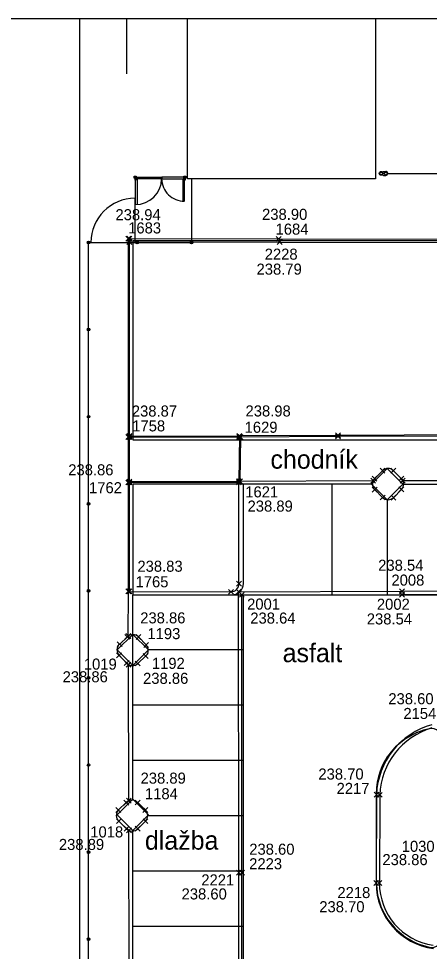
# Model space of a CAD drawing. Extents: x -264165 to -263733, y -1242319 to -1242245.
# Drawn here: x -263975.23 to -263956.67, y -1242287.11 to -1242244.94 of the extents above; entities that cross this region are included whole.
import ezdxf

# ---------------------------------------------------------------- set-up
doc = ezdxf.new("R2010")
doc.units = 0
for name, color, linetype in [('KFA_BOD_CISLO', 7, 'Continuous'), ('KFA_BOD_SYMBOL', 7, 'Continuous'), ('KFA_BOD_VYSKA', 7, 'Continuous'), ('KFA_SO_20-2_OBRUBNIKY_DOLNA_HRANA', 7, 'Continuous'), ('KFA_SO_20-2_OBRUBNIKY_HORNA_HRANA', 7, 'Continuous'), ('POPIS', 7, 'Continuous'), ('PROJEKT_OBRUBNIKY_KOMUNIKACIE', 7, 'Continuous'), ('PROJEKT_TDZ_VODOROVNE', 7, 'Continuous'), ('RAM_NA_TLAC_1-250', 7, 'Continuous'), ('SITUACIA_DSP_2D', 7, 'Continuous')]:
    doc.layers.add(name, color=color, linetype=linetype)

msp = doc.modelspace()

# ---------------------------------------------------------------- linework, layer by layer
at = {"layer": 'KFA_BOD_SYMBOL'}
for p, q in [((-263970.381, -1242254.992), (-263970.16, -1242254.771)), ((-263970.16, -1242254.992), (-263970.381, -1242254.771)), ((-263970.335, -1242254.992), (-263970.114, -1242254.772)), ((-263970.114, -1242254.992), (-263970.335, -1242254.772)), ((-263970.335, -1242255.14), (-263970.114, -1242254.918)), ((-263970.114, -1242255.14), (-263970.335, -1242254.918)), ((-263963.594, -1242255.002), (-263963.372, -1242254.782)), ((-263963.372, -1242255.002), (-263963.594, -1242254.782)), ((-263963.541, -1242255.146), (-263963.319, -1242254.924)), ((-263963.319, -1242255.146), (-263963.541, -1242254.924)), ((-263970.383, -1242263.964), (-263970.161, -1242263.742)), ((-263970.161, -1242263.964), (-263970.383, -1242263.742)), ((-263970.338, -1242263.917), (-263970.117, -1242263.697)), ((-263970.117, -1242263.917), (-263970.338, -1242263.697)), ((-263970.338, -1242263.965), (-263970.117, -1242263.744)), ((-263970.117, -1242263.965), (-263970.338, -1242263.744)), ((-263965.366, -1242263.961), (-263965.144, -1242263.74)), ((-263965.144, -1242263.961), (-263965.366, -1242263.74)), ((-263965.365, -1242263.913), (-263965.144, -1242263.691)), ((-263965.144, -1242263.913), (-263965.365, -1242263.691)), ((-263965.316, -1242263.963), (-263965.095, -1242263.742)), ((-263965.095, -1242263.963), (-263965.316, -1242263.742)), ((-263960.902, -1242263.887), (-263960.681, -1242263.667)), ((-263960.681, -1242263.887), (-263960.902, -1242263.667)), ((-263960.902, -1242263.938), (-263960.681, -1242263.717)), ((-263960.681, -1242263.938), (-263960.902, -1242263.717)), ((-263958.895, -1242265.487), (-263958.674, -1242265.265)), ((-263958.674, -1242265.487), (-263958.895, -1242265.265)), ((-263958.402, -1242265.485), (-263958.181, -1242265.264)), ((-263958.181, -1242265.485), (-263958.402, -1242265.264)), ((-263970.383, -1242266.016), (-263970.161, -1242265.796)), ((-263970.161, -1242266.016), (-263970.383, -1242265.796)), ((-263970.338, -1242265.972), (-263970.117, -1242265.752)), ((-263970.117, -1242265.972), (-263970.338, -1242265.752)), ((-263970.338, -1242266.018), (-263970.117, -1242265.796)), ((-263970.117, -1242266.018), (-263970.338, -1242265.796)), ((-263965.387, -1242265.965), (-263965.166, -1242265.744)), ((-263965.166, -1242265.965), (-263965.387, -1242265.744)), ((-263965.387, -1242266.008), (-263965.166, -1242265.788)), ((-263965.166, -1242266.008), (-263965.387, -1242265.788)), ((-263965.337, -1242265.965), (-263965.116, -1242265.744)), ((-263965.116, -1242265.965), (-263965.337, -1242265.744)), ((-263959.315, -1242265.933), (-263959.094, -1242265.711)), ((-263959.094, -1242265.933), (-263959.315, -1242265.711)), ((-263959.257, -1242265.849), (-263959.035, -1242265.627)), ((-263959.035, -1242265.849), (-263959.257, -1242265.627)), ((-263958.046, -1242265.838), (-263957.825, -1242265.617)), ((-263957.825, -1242265.838), (-263958.046, -1242265.617)), ((-263957.978, -1242265.934), (-263957.757, -1242265.713)), ((-263957.757, -1242265.934), (-263957.978, -1242265.713)), ((-263959.245, -1242266.34), (-263959.024, -1242266.12)), ((-263959.024, -1242266.34), (-263959.245, -1242266.12)), ((-263958.039, -1242266.333), (-263957.818, -1242266.112)), ((-263957.818, -1242266.333), (-263958.039, -1242266.112)), ((-263958.889, -1242266.695), (-263958.667, -1242266.475)), ((-263958.667, -1242266.695), (-263958.889, -1242266.475)), ((-263958.398, -1242266.705), (-263958.177, -1242266.485)), ((-263958.177, -1242266.705), (-263958.398, -1242266.485)), ((-263965.386, -1242270.599), (-263965.165, -1242270.377)), ((-263965.165, -1242270.599), (-263965.386, -1242270.377)), ((-263970.381, -1242270.943), (-263970.16, -1242270.721)), ((-263970.16, -1242270.943), (-263970.381, -1242270.721)), ((-263970.338, -1242270.943), (-263970.117, -1242270.721)), ((-263970.117, -1242270.943), (-263970.338, -1242270.721)), ((-263965.747, -1242270.961), (-263965.525, -1242270.74)), ((-263965.525, -1242270.961), (-263965.747, -1242270.74)), ((-263965.399, -1242270.957), (-263965.178, -1242270.735)), ((-263965.178, -1242270.957), (-263965.399, -1242270.735)), ((-263965.253, -1242271.097), (-263965.032, -1242270.877)), ((-263965.032, -1242271.097), (-263965.253, -1242270.877)), ((-263958.011, -1242270.936), (-263957.79, -1242270.715)), ((-263957.79, -1242270.936), (-263958.011, -1242270.715)), ((-263958.009, -1242271.088), (-263957.788, -1242270.867)), ((-263957.788, -1242271.088), (-263958.009, -1242270.867)), ((-263970.777, -1242273.329), (-263970.556, -1242273.107)), ((-263970.556, -1242273.329), (-263970.777, -1242273.107)), ((-263970.429, -1242272.998), (-263970.208, -1242272.776)), ((-263970.208, -1242272.998), (-263970.429, -1242272.776)), ((-263970.387, -1242272.961), (-263970.166, -1242272.741)), ((-263970.166, -1242272.961), (-263970.387, -1242272.741)), ((-263969.924, -1242273.002), (-263969.703, -1242272.782)), ((-263969.703, -1242273.002), (-263969.924, -1242272.782)), ((-263969.578, -1242273.365), (-263969.356, -1242273.144)), ((-263969.356, -1242273.365), (-263969.578, -1242273.144)), ((-263970.802, -1242273.832), (-263970.581, -1242273.61)), ((-263970.581, -1242273.832), (-263970.802, -1242273.61)), ((-263969.599, -1242273.863), (-263969.378, -1242273.641)), ((-263969.378, -1242273.863), (-263969.599, -1242273.641)), ((-263970.464, -1242274.187), (-263970.242, -1242273.965)), ((-263970.242, -1242274.187), (-263970.464, -1242273.965)), ((-263970.378, -1242274.255), (-263970.156, -1242274.034)), ((-263970.156, -1242274.255), (-263970.378, -1242274.034)), ((-263969.958, -1242274.201), (-263969.736, -1242273.981)), ((-263969.736, -1242274.201), (-263969.958, -1242273.981)), ((-263970.48, -1242280.495), (-263970.258, -1242280.274)), ((-263970.258, -1242280.495), (-263970.48, -1242280.274)), ((-263970.36, -1242280.41), (-263970.139, -1242280.19)), ((-263970.139, -1242280.41), (-263970.36, -1242280.19)), ((-263969.967, -1242280.488), (-263969.746, -1242280.266)), ((-263969.746, -1242280.488), (-263969.967, -1242280.266)), ((-263959.165, -1242280.14), (-263958.943, -1242279.918)), ((-263958.943, -1242280.14), (-263959.165, -1242279.918)), ((-263959.017, -1242280.14), (-263958.796, -1242279.92)), ((-263958.796, -1242280.14), (-263959.017, -1242279.92)), ((-263970.833, -1242280.826), (-263970.611, -1242280.606)), ((-263970.611, -1242280.826), (-263970.833, -1242280.606)), ((-263969.612, -1242280.826), (-263969.391, -1242280.606)), ((-263969.391, -1242280.826), (-263969.612, -1242280.606)), ((-263970.816, -1242281.335), (-263970.595, -1242281.113)), ((-263970.595, -1242281.335), (-263970.816, -1242281.113)), ((-263969.607, -1242281.333), (-263969.386, -1242281.113)), ((-263969.386, -1242281.333), (-263969.607, -1242281.113)), ((-263970.465, -1242281.676), (-263970.244, -1242281.454)), ((-263970.244, -1242281.676), (-263970.465, -1242281.454)), ((-263970.359, -1242281.748), (-263970.138, -1242281.528)), ((-263970.138, -1242281.748), (-263970.359, -1242281.528)), ((-263969.958, -1242281.674), (-263969.736, -1242281.453)), ((-263969.736, -1242281.674), (-263969.958, -1242281.453)), ((-263965.389, -1242283.66), (-263965.168, -1242283.44)), ((-263965.168, -1242283.66), (-263965.389, -1242283.44)), ((-263965.247, -1242283.663), (-263965.026, -1242283.441)), ((-263965.026, -1242283.663), (-263965.247, -1242283.441)), ((-263959.181, -1242284.127), (-263958.959, -1242283.906)), ((-263958.959, -1242284.127), (-263959.181, -1242283.906)), ((-263959.036, -1242284.127), (-263958.815, -1242283.906)), ((-263958.815, -1242284.127), (-263959.036, -1242283.906))]:
    msp.add_line(p, q, dxfattribs=at)
at = {"layer": 'KFA_SO_20-2_OBRUBNIKY_DOLNA_HRANA'}
msp.add_line((-263959.054, -1242280.029), (-263959.07, -1242284.016), dxfattribs=at)
for points in [[(-263970.225, -1242255.029), (-263963.43, -1242255.035), (-263953.224, -1242255.054), (-263930.231, -1242255.088)], [(-263965.289, -1242270.846), (-263957.9, -1242270.825), (-263950.806, -1242270.811), (-263943.808, -1242270.801), (-263936.795, -1242270.772), (-263929.578, -1242270.752)], [(-263965.273, -1242293.566), (-263965.279, -1242283.55), (-263965.289, -1242270.846)], [(-263965.143, -1242270.987), (-263957.899, -1242270.977), (-263950.804, -1242270.956), (-263943.803, -1242270.944), (-263936.794, -1242270.917), (-263929.31, -1242270.895)], [(-263965.127, -1242293.556), (-263965.137, -1242283.552), (-263965.143, -1242270.987)]]:
    msp.add_lwpolyline(points, dxfattribs=at)
for centre, major_axis, ratio, start_param, end_param in [((-263955.655, -1242280.15), (-0.469, 3.371), 0.999366, 0.126889, 1.396912), ((-263956.094, -1242284.026), (2.785, -1.049), 0.999986, 3.498387, 4.942262)]:
    msp.add_ellipse(centre, major_axis=major_axis, ratio=ratio, start_param=start_param, end_param=end_param, dxfattribs=at)
at = {"layer": 'KFA_SO_20-2_OBRUBNIKY_HORNA_HRANA'}
for p, q in [((-263970.27, -1242254.881), (-263970.225, -1242254.882)), ((-263970.227, -1242263.807), (-263965.254, -1242263.802)), ((-263970.227, -1242263.854), (-263965.255, -1242263.85)), ((-263970.227, -1242265.862), (-263965.276, -1242265.854)), ((-263970.227, -1242265.907), (-263965.276, -1242265.898)), ((-263965.276, -1242265.854), (-263959.204, -1242265.822)), ((-263965.275, -1242270.488), (-263965.276, -1242265.854)), ((-263957.867, -1242265.823), (-263950.988, -1242265.812)), ((-263959.134, -1242266.23), (-263958.778, -1242266.585)), ((-263970.666, -1242273.218), (-263970.318, -1242272.887)), ((-263969.813, -1242272.892), (-263969.467, -1242273.254)), ((-263970.692, -1242273.721), (-263970.353, -1242274.076)), ((-263969.488, -1242273.752), (-263969.847, -1242274.091)), ((-263970.249, -1242280.3), (-263970.267, -1242274.144)), ((-263958.906, -1242280.03), (-263958.926, -1242284.016)), ((-263970.722, -1242280.716), (-263970.369, -1242280.384)), ((-263969.856, -1242280.377), (-263969.502, -1242280.716)), ((-263970.355, -1242281.565), (-263970.705, -1242281.224)), ((-263969.497, -1242281.223), (-263969.847, -1242281.563)), ((-263970.239, -1242287.847), (-263970.248, -1242281.638))]:
    msp.add_line(p, q, dxfattribs=at)
for points in [[(-263970.27, -1242270.832), (-263970.272, -1242265.906), (-263970.272, -1242263.853), (-263970.27, -1242254.881)], [(-263970.227, -1242270.832), (-263970.227, -1242265.907), (-263970.227, -1242263.854), (-263970.225, -1242254.882)], [(-263970.225, -1242254.882), (-263963.483, -1242254.892), (-263953.227, -1242254.91), (-263930.229, -1242254.938)], [(-263927.032, -1242263.694), (-263929.858, -1242263.715), (-263931.859, -1242263.708), (-263939.843, -1242263.726), (-263948.832, -1242263.749), (-263954.816, -1242263.759), (-263960.791, -1242263.777), (-263965.254, -1242263.802), (-263965.276, -1242265.854)], [(-263927.18, -1242263.745), (-263929.889, -1242263.765), (-263931.859, -1242263.758), (-263939.843, -1242263.776), (-263948.832, -1242263.799), (-263954.816, -1242263.809), (-263960.791, -1242263.827), (-263965.205, -1242263.852), (-263965.226, -1242265.854)], [(-263958.785, -1242265.376), (-263959.146, -1242265.738)], [(-263957.936, -1242265.727), (-263958.291, -1242265.374)], [(-263958.287, -1242266.595), (-263957.928, -1242266.222)], [(-263970.276, -1242272.851), (-263970.27, -1242270.832), (-263965.636, -1242270.85)]]:
    msp.add_lwpolyline(points, dxfattribs=at)
for centre, major_axis, ratio, start_param, end_param in [((-263958.537, -1242265.623), (-0.323, 0.135), 0.999783, 4.328397, 5.895389), ((-263958.886, -1242265.978), (-0.181, -0.304), 0.999535, 4.506104, 6.043127), ((-263958.187, -1242265.979), (-0.251, 0.252), 0.999847, 3.1764, 4.716307), ((-263958.527, -1242266.332), (0.22, -0.28), 0.999969, 4.836879, 6.356561), ((-263965.627, -1242270.498), (0.328, 0.126), 0.999435, 4.318529, 5.945352), ((-263970.068, -1242273.142), (-0.343, 0.098), 0.999556, 4.196305, 5.766372), ((-263970.439, -1242273.482), (-0.048, -0.345), 0.999733, 3.988836, 5.608141), ((-263969.725, -1242273.493), (0.001, -0.352), 0.999056, 0.736918, 2.312272), ((-263970.093, -1242273.839), (0.352, -0.01), 0.999301, 3.910899, 5.513879), ((-263955.636, -1242280.153), (0.058, 3.275), 0.999165, 0.301718, 1.55091), ((-263970.109, -1242280.629), (-0.352, 0.061), 0.99949, 4.094713, 5.698395), ((-263970.467, -1242280.962), (0.236, -0.264), 0.999925, 3.215899, 4.816729), ((-263969.757, -1242280.972), (0.062, 0.356), 0.999459, 4.116697, 5.669865), ((-263970.102, -1242281.31), (-0.343, -0.109), 0.999217, 0.483156, 2.052302), ((-263956.072, -1242284.009), (-2.548, 1.287), 0.999996, 0.470217, 1.888537)]:
    msp.add_ellipse(centre, major_axis=major_axis, ratio=ratio, start_param=start_param, end_param=end_param, dxfattribs=at)
at = {"layer": 'PROJEKT_OBRUBNIKY_KOMUNIKACIE'}
for p, q in [((-263959.275, -1242265.982), (-263970.068, -1242265.982)), ((-263965.068, -1242270.482), (-263965.068, -1242265.982)), ((-263957.861, -1242265.982), (-263951.031, -1242265.982)), ((-263970.065, -1242280.238), (-263970.068, -1242270.982)), ((-263965.568, -1242270.982), (-263929.061, -1242270.982)), ((-263965.068, -1242293.482), (-263965.068, -1242270.982)), ((-263957.228, -1242277.216), (-263957.743, -1242277.494)), ((-263956.668, -1242277.043), (-263957.228, -1242277.216)), ((-263956.58, -1242277.033), (-263956.668, -1242277.043)), ((-263957.743, -1242277.494), (-263958.195, -1242277.867)), ((-263958.195, -1242277.867), (-263958.566, -1242278.321)), ((-263958.566, -1242278.321), (-263958.841, -1242278.838)), ((-263958.841, -1242278.838), (-263959.011, -1242279.399)), ((-263959.011, -1242279.399), (-263959.068, -1242279.982)), ((-263959.068, -1242279.982), (-263959.068, -1242283.982)), ((-263970.068, -1242287.775), (-263970.068, -1242281.649)), ((-263959.068, -1242283.982), (-263959.011, -1242284.565)), ((-263959.011, -1242284.565), (-263958.841, -1242285.126)), ((-263958.841, -1242285.126), (-263958.566, -1242285.644)), ((-263958.566, -1242285.644), (-263958.195, -1242286.098)), ((-263958.195, -1242286.098), (-263957.743, -1242286.471)), ((-263957.743, -1242286.471), (-263957.228, -1242286.749)), ((-263957.228, -1242286.749), (-263956.668, -1242286.922)), ((-263956.668, -1242286.922), (-263956.58, -1242286.932))]:
    msp.add_line(p, q, dxfattribs=at)
for points in [[(-264042.568, -1242294.032), (-263972.468, -1242294.032), (-263972.468, -1242244.935)], [(-263959.097, -1242244.935), (-263959.097, -1242252.182), (-263967.597, -1242252.182), (-263967.597, -1242244.935)], [(-263929.58, -1242254.982), (-263970.077, -1242254.982), (-263970.077, -1242263.982), (-263929.58, -1242263.982), (-263929.58, -1242254.982)], [(-263958.568, -1242265.275), (-263957.861, -1242265.982), (-263958.568, -1242266.689), (-263959.275, -1242265.982), (-263958.568, -1242265.275)], [(-263970.068, -1242265.982), (-263970.068, -1242270.982), (-263965.568, -1242270.982)], [(-263970.068, -1242272.775), (-263969.361, -1242273.482), (-263970.068, -1242274.189), (-263970.775, -1242273.482), (-263970.068, -1242272.775)], [(-263970.068, -1242280.235), (-263969.361, -1242280.942), (-263970.068, -1242281.649), (-263970.775, -1242280.942), (-263970.068, -1242280.235)]]:
    msp.add_lwpolyline(points, dxfattribs=at)
msp.add_arc((-263965.568, -1242270.482), 0.5, 270, 0, dxfattribs=at)
at = {"layer": 'PROJEKT_TDZ_VODOROVNE'}
for p, q in [((-263961.068, -1242265.982), (-263961.068, -1242270.982)), ((-263958.568, -1242266.689), (-263958.568, -1242270.982)), ((-263965.068, -1242273.482), (-263969.361, -1242273.482)), ((-263965.068, -1242275.982), (-263970.068, -1242275.982)), ((-263965.068, -1242278.482), (-263970.068, -1242278.482)), ((-263965.068, -1242280.982), (-263969.401, -1242280.982)), ((-263965.068, -1242283.482), (-263970.068, -1242283.482)), ((-263965.068, -1242285.982), (-263970.068, -1242285.982))]:
    msp.add_line(p, q, dxfattribs=at)
at = {"layer": 'RAM_NA_TLAC_1-250'}
msp.add_line((-263970.363, -1242244.935), (-263970.363, -1242247.435), dxfattribs=at)
msp.add_lwpolyline([(-264165.363, -1242244.935), (-263732.863, -1242244.935), (-263732.863, -1242319.185), (-264165.363, -1242319.185)], close=True, dxfattribs=at)
at = {"layer": 'SITUACIA_DSP_2D'}
for p, q in [((-263972.468, -1242294.032), (-263972.468, -1242244.935)), ((-263972.468, -1242244.935), (-263972.468, -1242244.935)), ((-263967.597, -1242252.182), (-263967.597, -1242244.935)), ((-263967.597, -1242244.935), (-263967.597, -1242244.935)), ((-263967.593, -1242252.182), (-263967.593, -1242244.935)), ((-263967.593, -1242252.182), (-263967.593, -1242244.935)), ((-263959.097, -1242244.935), (-263959.097, -1242244.935)), ((-263959.097, -1242244.935), (-263959.097, -1242252.182)), ((-263959.093, -1242244.935), (-263959.093, -1242252.182)), ((-263959.093, -1242244.935), (-263959.093, -1242252.182)), ((-263958.799, -1242251.862), (-263958.762, -1242251.862)), ((-263958.799, -1242252.002), (-263958.762, -1242252.002)), ((-263958.762, -1242251.862), (-263958.742, -1242251.842)), ((-263958.762, -1242252.002), (-263958.742, -1242252.022)), ((-263958.742, -1242251.842), (-263958.637, -1242251.842)), ((-263958.575, -1242251.932), (-263952.5, -1242251.932)), ((-263970.018, -1242252.152), (-263970.018, -1242252.052)), ((-263970.018, -1242252.052), (-263969.918, -1242252.052)), ((-263969.918, -1242252.152), (-263970.018, -1242252.152)), ((-263970.005, -1242252.14), (-263970.005, -1242252.065)), ((-263970.005, -1242252.065), (-263969.93, -1242252.065)), ((-263969.93, -1242252.14), (-263970.005, -1242252.14)), ((-263969.93, -1242252.14), (-263969.98, -1242252.14)), ((-263969.98, -1242252.14), (-263969.98, -1242252.24)), ((-263969.98, -1242252.24), (-263969.955, -1242252.24)), ((-263969.968, -1242252.152), (-263969.968, -1242252.202)), ((-263969.968, -1242252.202), (-263969.868, -1242252.202)), ((-263969.955, -1242253.327), (-263969.955, -1242252.19)), ((-263969.955, -1242252.19), (-263969.88, -1242252.19)), ((-263969.93, -1242252.065), (-263969.93, -1242252.14)), ((-263969.918, -1242252.052), (-263969.918, -1242252.152)), ((-263969.918, -1242252.102), (-263968.78, -1242252.102)), ((-263969.918, -1242252.177), (-263969.918, -1242252.102)), ((-263968.78, -1242252.177), (-263969.918, -1242252.177)), ((-263969.88, -1242252.19), (-263969.88, -1242253.327)), ((-263969.868, -1242252.202), (-263969.868, -1242252.177)), ((-263968.78, -1242252.102), (-263968.78, -1242252.177)), ((-263967.768, -1242252.102), (-263968.755, -1242252.102)), ((-263968.755, -1242252.102), (-263968.755, -1242252.177)), ((-263968.755, -1242252.177), (-263967.768, -1242252.177)), ((-263967.818, -1242252.202), (-263967.818, -1242252.177)), ((-263967.718, -1242252.202), (-263967.818, -1242252.202)), ((-263967.805, -1242252.19), (-263967.807, -1242253.177)), ((-263967.73, -1242252.19), (-263967.805, -1242252.19)), ((-263967.768, -1242252.152), (-263967.768, -1242252.052)), ((-263967.768, -1242252.052), (-263967.668, -1242252.052)), ((-263967.768, -1242252.177), (-263967.768, -1242252.102)), ((-263967.668, -1242252.152), (-263967.768, -1242252.152)), ((-263967.755, -1242252.14), (-263967.755, -1242252.065)), ((-263967.755, -1242252.065), (-263967.68, -1242252.065)), ((-263967.755, -1242252.14), (-263967.705, -1242252.14)), ((-263967.68, -1242252.14), (-263967.755, -1242252.14)), ((-263967.732, -1242253.177), (-263967.73, -1242252.19)), ((-263967.705, -1242252.24), (-263967.73, -1242252.24)), ((-263967.718, -1242252.152), (-263967.718, -1242252.202)), ((-263967.705, -1242252.14), (-263967.705, -1242252.24)), ((-263967.68, -1242252.065), (-263967.68, -1242252.14)), ((-263967.668, -1242252.052), (-263967.668, -1242252.152)), ((-263959.097, -1242252.182), (-263967.597, -1242252.182)), ((-263959.093, -1242252.182), (-263967.593, -1242252.182)), ((-263959.093, -1242252.182), (-263967.593, -1242252.182)), ((-263967.418, -1242252.182), (-263967.418, -1242255.057)), ((-263958.742, -1242252.022), (-263958.637, -1242252.022)), ((-263969.968, -1242255.057), (-263969.968, -1242253.057)), ((-263972.128, -1242255.057), (-263972.008, -1242255.057)), ((-263972.068, -1242255.117), (-263972.068, -1242254.997)), ((-263972.068, -1242255.057), (-263967.418, -1242255.057)), ((-263972.068, -1242294.432), (-263972.068, -1242255.057)), ((-263969.928, -1242255.057), (-263969.808, -1242255.057)), ((-263969.868, -1242255.117), (-263969.868, -1242254.997)), ((-263967.478, -1242255.057), (-263967.358, -1242255.057)), ((-263967.418, -1242255.117), (-263967.418, -1242254.997)), ((-263972.128, -1242258.995), (-263972.008, -1242258.995)), ((-263972.068, -1242259.055), (-263972.068, -1242258.935)), ((-263972.128, -1242262.932), (-263972.008, -1242262.932)), ((-263972.068, -1242262.992), (-263972.068, -1242262.872)), ((-263965.068, -1242265.982), (-263970.068, -1242265.982)), ((-263965.068, -1242270.482), (-263965.068, -1242265.982)), ((-263972.128, -1242266.87), (-263972.008, -1242266.87)), ((-263972.068, -1242266.93), (-263972.068, -1242266.81)), ((-263972.128, -1242270.807), (-263972.008, -1242270.807)), ((-263972.068, -1242270.867), (-263972.068, -1242270.747)), ((-263970.065, -1242280.238), (-263970.068, -1242270.982)), ((-263972.128, -1242274.745), (-263972.008, -1242274.745)), ((-263972.068, -1242274.805), (-263972.068, -1242274.685)), ((-263972.128, -1242278.682), (-263972.008, -1242278.682)), ((-263972.068, -1242278.742), (-263972.068, -1242278.622)), ((-263959.068, -1242279.982), (-263959.068, -1242283.982)), ((-263970.068, -1242287.775), (-263970.068, -1242281.649)), ((-263972.128, -1242282.62), (-263972.008, -1242282.62)), ((-263972.068, -1242282.68), (-263972.068, -1242282.56)), ((-263972.128, -1242286.557), (-263972.008, -1242286.557)), ((-263972.068, -1242286.617), (-263972.068, -1242286.497))]:
    msp.add_line(p, q, dxfattribs=at)
for points in [[(-263929.58, -1242254.982), (-263970.077, -1242254.982), (-263970.077, -1242263.982), (-263929.58, -1242263.982), (-263929.58, -1242254.982)], [(-263970.068, -1242265.982), (-263970.068, -1242270.982), (-263965.568, -1242270.982)]]:
    msp.add_lwpolyline(points, dxfattribs=at)
for points in [[(-263958.568, -1242265.275), (-263957.861, -1242265.982), (-263958.568, -1242266.689), (-263959.275, -1242265.982)], [(-263970.068, -1242272.775), (-263969.361, -1242273.482), (-263970.068, -1242274.189), (-263970.775, -1242273.482)], [(-263970.068, -1242280.235), (-263969.361, -1242280.942), (-263970.068, -1242281.649), (-263970.775, -1242280.942)]]:
    msp.add_lwpolyline(points, close=True, dxfattribs=at)
for centre, radius in [((-263958.847, -1242251.932), 0.085), ((-263958.847, -1242251.932), 0.0625), ((-263958.637, -1242251.932), 0.0625), ((-263972.068, -1242255.057), 0.06), ((-263969.868, -1242255.057), 0.06), ((-263967.418, -1242255.057), 0.06), ((-263972.068, -1242258.995), 0.06), ((-263972.068, -1242262.932), 0.06), ((-263972.068, -1242266.87), 0.06), ((-263972.068, -1242270.807), 0.06), ((-263972.068, -1242274.745), 0.06), ((-263972.068, -1242278.682), 0.06), ((-263972.068, -1242282.62), 0.06), ((-263972.068, -1242286.557), 0.06)]:
    msp.add_circle(centre, radius, dxfattribs=at)
for centre, radius, start, end in [((-263958.637, -1242251.932), 0.09, 270, 90), ((-263969.943, -1242252.165), 1.175, 269.3905, 359.3905), ((-263967.743, -1242252.165), 1.025, 180.6095, 270.6095), ((-263969.968, -1242255.057), 2, 90, 180), ((-263965.568, -1242270.482), 0.5, 270, 0), ((-263956.068, -1242279.982), 3, 101.537, 180), ((-263956.568, -1242277.533), 0.5, 0, 101.537), ((-263956.068, -1242283.982), 3, 180, 258.463), ((-263956.568, -1242286.432), 0.5, 258.463, 0)]:
    msp.add_arc(centre, radius, start, end, dxfattribs=at)
for centre in [(-263969.943, -1242252.165), (-263969.943, -1242252.165), (-263967.743, -1242252.165)]:
    msp.add_ellipse(centre, major_axis=(0, 0.0125), ratio=0.999995, dxfattribs=at)

# ---------------------------------------------------------------- texts
at = {"layer": 'KFA_BOD_CISLO'}
for s, p in [('1683', (-263970.282, -1242254.648)), ('1684', (-263963.619, -1242254.702)), ('2228', (-263964.109, -1242255.834)), ('1758', (-263970.098, -1242263.599)), ('1629', (-263965.017, -1242263.661)), ('1762', (-263972.051, -1242266.394)), ('1621', (-263964.988, -1242266.583)), ('1765', (-263969.948, -1242270.647)), ('2008', (-263958.38, -1242270.572)), ('2001', (-263964.905, -1242271.658)), ('2002', (-263959.037, -1242271.663)), ('1193', (-263969.411, -1242272.993)), ('1019', (-263972.286, -1242274.371)), ('1192', (-263969.21, -1242274.335)), ('2154', (-263957.84, -1242276.603)), ('1184', (-263969.523, -1242280.232)), ('2217', (-263960.859, -1242279.99)), ('1018', (-263971.994, -1242281.958)), ('1030', (-263957.915, -1242282.61)), ('2223', (-263964.811, -1242283.398)), ('2221', (-263966.975, -1242284.129)), ('2218', (-263960.823, -1242284.701))]:
    msp.add_text(s, height=0.5, dxfattribs=at).set_placement(p)
at = {"layer": 'KFA_BOD_VYSKA'}
for s, p in [('238.94', (-263970.856, -1242254.049)), ('238.90', (-263964.228, -1242254.032)), ('238.79', (-263964.478, -1242256.511)), ('238.87', (-263970.116, -1242262.927)), ('238.98', (-263964.976, -1242262.924)), ('238.86', (-263972.99, -1242265.585)), ('238.89', (-263964.884, -1242267.225)), ('238.83', (-263969.864, -1242269.945)), ('238.54', (-263958.979, -1242269.901)), ('238.86', (-263969.737, -1242272.28)), ('238.64', (-263964.761, -1242272.289)), ('238.54', (-263959.494, -1242272.328)), ('238.86', (-263973.246, -1242274.944)), ('238.86', (-263969.608, -1242275.014)), ('238.60', (-263958.519, -1242275.936)), ('238.70', (-263961.682, -1242279.341)), ('238.89', (-263969.721, -1242279.527)), ('238.89', (-263973.414, -1242282.525)), ('238.60', (-263964.808, -1242282.74)), ('238.86', (-263958.788, -1242283.212)), ('238.60', (-263967.867, -1242284.763)), ('238.70', (-263961.641, -1242285.341))]:
    msp.add_text(s, height=0.5, dxfattribs=at).set_placement(p)
at = {"layer": 'POPIS'}
for s, p in [('chodník', (-263963.849, -1242265.285)), ('asfalt', (-263963.298, -1242274.034)), ('dlažba', (-263969.526, -1242282.512))]:
    msp.add_text(s, height=0.8438, dxfattribs=at).set_placement(p)

doc.saveas('drawing.dxf')
